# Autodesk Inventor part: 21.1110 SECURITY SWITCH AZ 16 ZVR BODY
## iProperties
Created: 2007-05
Part Number: 21.1110 SECURITY SWITCH AZ 16 ZVR BODY
Material: ABS Plastic
Document SubType Name: Modeling
Designer: Andy Moles
Mass: 125.024 g
Surface Area: 230.094 cm^2
Volume: 117.947 cm^3
Density: 1.06 g/cm^3
Author: Andy Moles
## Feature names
1. Base1
